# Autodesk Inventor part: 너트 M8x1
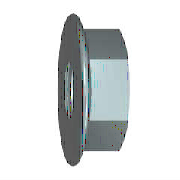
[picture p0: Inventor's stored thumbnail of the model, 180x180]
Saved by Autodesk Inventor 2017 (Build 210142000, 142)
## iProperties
Created: 2015-12
Part Number: 너트 M8x1
Material: 스테인리스강
Description: 플랜지붙이 6각 너트 - 일반 스레드
Document SubType Name: Modeling
Standard: ISO 4161
Designer: mdu
Standard Revision: 2판 1999-03-15
Standards Organization: ISO
Language: ko-KR
Size Designation: M8
Categories: <MemberInstance><Categories><Category DisplayName="조임쇠" InternalName="e4da775c-781d-43d5-af7c-5136215cf5a6" Mnemonic="FSTN"><Category DisplayName="너트" InternalN
Density: 8.08 g/cm^3
Mass: 9.03298 g
Surface Area: 8.90186 cm^2
Volume: 1.11794 cm^3
Appearance: 기본값
Author: mdu
IsCustomPart: 1
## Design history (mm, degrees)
sketch "스케치1"
  geometry: L1 (-1.844, 0)-(9.641, 0) reference; L2 (3.107, 6.5)-(2.288, 8.257); L3 (3.107, 6.5)-(8, 6.5); L4 (8, 6.5)-(8, 0); L5 (3.107, 6.5)-(3.107, 0); L6 (0, -1.835)-(0, 11.01) reference; A1 r 1.2 centre (1.2, 7.75) between (2.288, 8.257) and (0, 7.75); 1 further point
  constraints: 8 end point, 3 point on line, 2 perpendicular, 2 point on circle, 2 tangent, 1 centre point, 1 parallel
  dimensions: "d2" = 13 diameter of L3 L1 (= SW); "d4" = 17.9 dimension on A1 L1 (= LADI); "d5" = 1.2 radius of A1 (= PHH); "d15" = 8 distance between parallel lines of L4 L6 (= KOH); "d16" = 25 deg angle of L6 L2 (= KEWI)
revolve "링" sketch "스케치1" stored, may be unused: angle "d8" = 90 deg
sketch "스케치2"
  geometry: L1 (-6.5, -3.753)-(-6.5, 3.753); L2 (-6.5, 3.753)-(0, 7.506); L3 (0, 7.506)-(6.5, 3.753); L4 (6.5, 3.753)-(6.5, -3.753); L5 (6.5, -3.753)-(0, -7.506); L6 (0, -7.506)-(-6.5, -3.753); C1 r 4.9 at (0, 0); C2 r 7.75 at (0, 0) reference; 1 further point
  constraints: 12 end point, 1 centre point, 1 coincident, 1 vertical, 11 other
  dimensions: "d6" = 15.01111 distance of L5.end L2.end (= 1.1547 x SW)
extrude "본체" join sketch "스케치2" distance "d7" = 8 (= KOH); taper "d9" = 0 deg
sketch "스케치3"
  geometry: L1 (2.638, 7.506)-(8, 7.506) reference; L2 (8, 3.753)-(8, 7.506) reference; L3 (0, -7.75)-(0, 7.75) reference; L4 (-1.6, 0)-(9.6, 0) reference; L5 (7.419, 7.506)-(8, 6.5)
  constraints: 2 end point, 2 point on line
  dimensions: "d10" = 30 deg angle of L2 L5 (= ANG1); "d11" = 13 diameter of L5.end L4 (= SW0)
revolve "모따기1" sketch "스케치3" stored, may be unused: angle "d24" = 90 deg
sketch "스케치4"
  geometry: C1 r 7.75 at (0, 0) reference; 1 further point
  constraints: 1 coincident
hole "스레드" sketch "스케치4" at (0, 0) diameter "d25" = 6.647; stored, may be unused: countersink angle "d29" = 82 deg, drill point angle "d31" = 118 deg; dims "d26" = 6, "d27" = 4, "d28" = 2, "d30" = 8
workaxis "Work Axis1"
workplane "Work Plane1"
body "Solid1"
chamfer "모따기2" distance "d12" = 0.67658 (= -0.5 x GD1 + 0.5 x NND); stored, may be unused: angle "d13" = 30 deg, second distance "d46" = 0.67658 (= -0.5 x GD1 + 0.5 x NND)
chamfer "모따기3" distance "d51" = 0.67658 (= -0.5 x GD1 + 0.5 x NND); stored, may be unused: second distance "d52" = 2, angle "d53" = 45 deg
other parameters: "ANG1" = 30 deg [user parameter; used in 1 equation term], "KEWI" = 25 deg [user parameter; used in 1 equation term], "NND" = 8 [user parameter; used in 4 equation terms], "LADI" = 17.9 [user parameter; used in 2 equation terms], "SW" = 13 [user parameter; used in 3 equation terms], "PHH" = 1.2 [user parameter; used in 3 equation terms], "KOH" = 8 (= NND) [user parameter; used in 2 equation terms], "SW0" = 13 [user parameter; used in 1 equation term], "GD1" = 6.64684 (computed from THREADDIA, PTC, TOA) [user parameter; used in 3 equation terms], "d1" = 17.9 (= LADI), "d3" = 1.2 (= PHH), "d45" = 0, "d47" = 0, "d49" = 0, "d54" = 0, "GUL" = 0.67658 (= 0.541266 x PTC) [user parameter], "TPU" = 8 (computed from PTC) [user parameter], "RR" = 1.2 (= PHH) [user parameter], "THREADDIA" = 8 [user parameter; used in 1 equation term], "TOA" = 30 deg [user parameter; used in 1 equation term], "PTC" = 1.25 [user parameter; used in 4 equation terms], "GAL" = 0.67658 (= 0.541266 x PTC) [user parameter], "E0" = 15.015 (= 1.155 x SW) [user parameter]
